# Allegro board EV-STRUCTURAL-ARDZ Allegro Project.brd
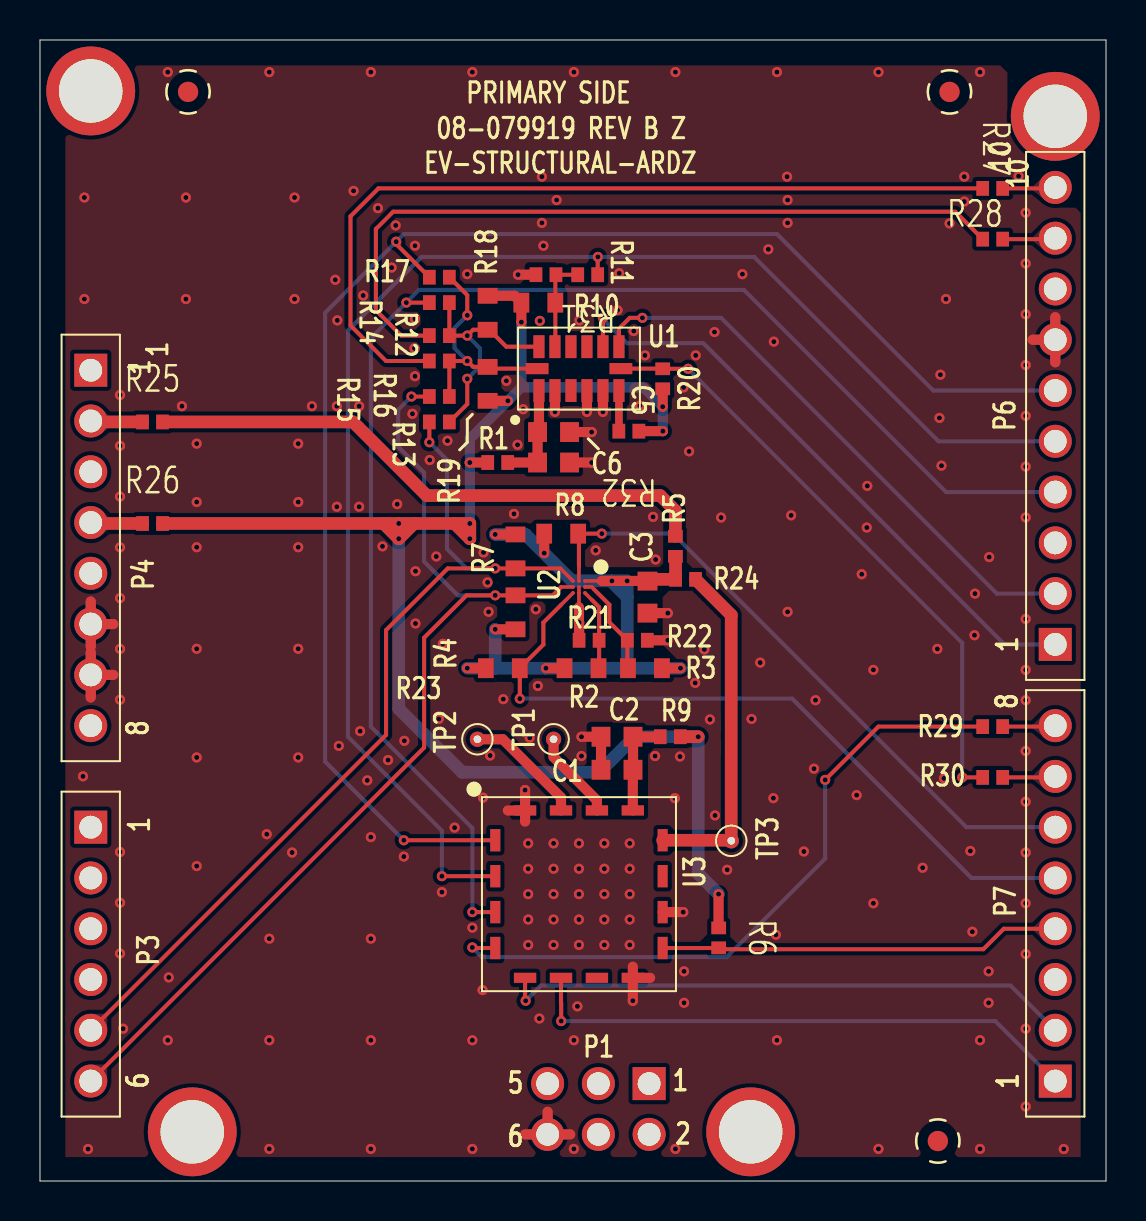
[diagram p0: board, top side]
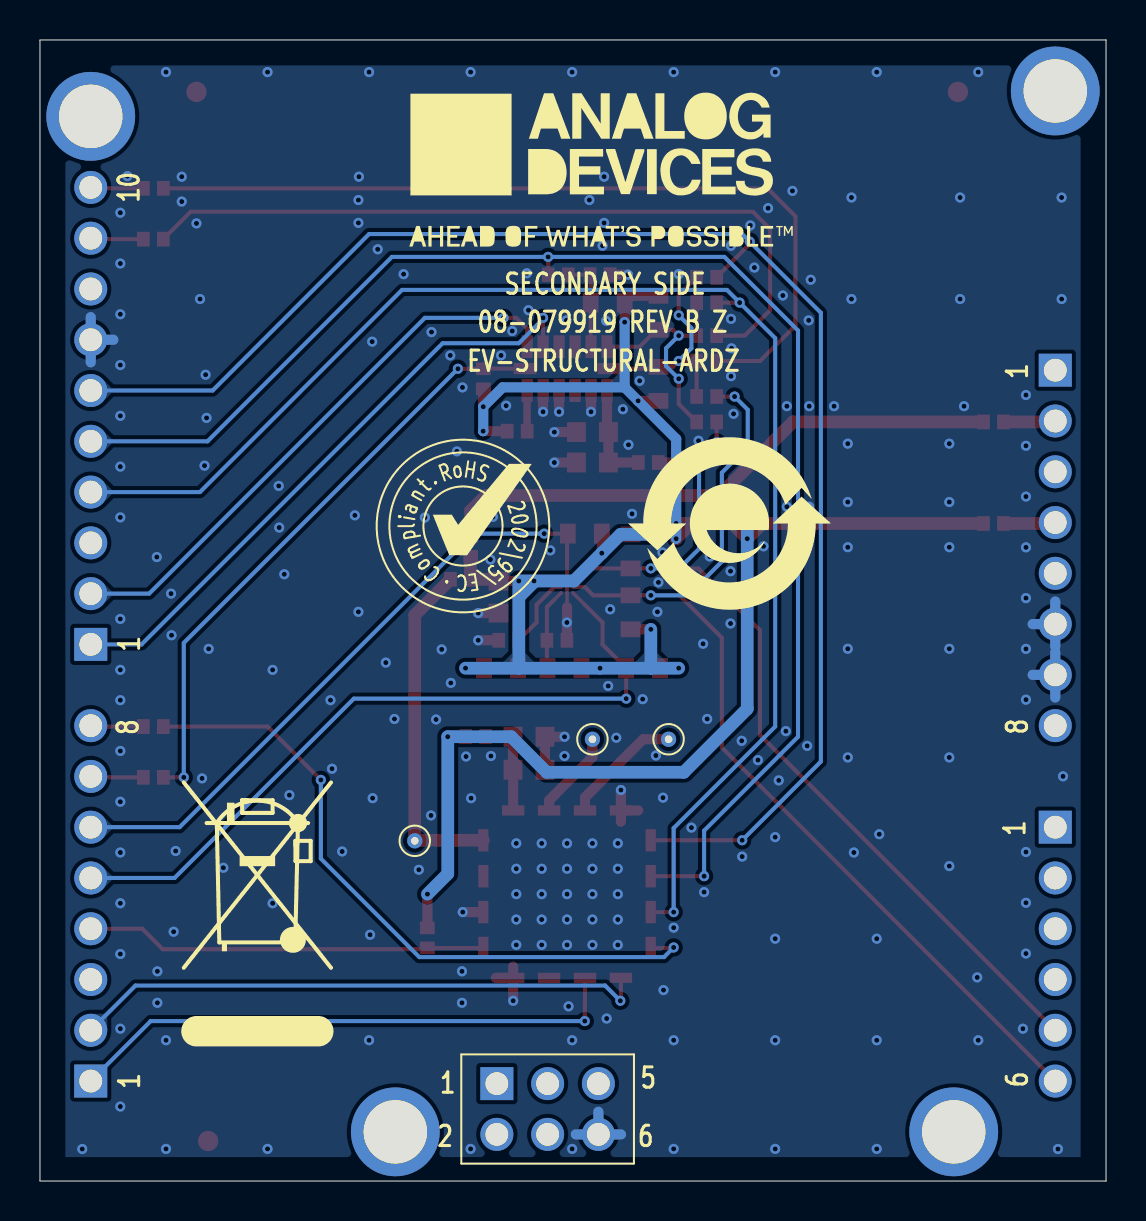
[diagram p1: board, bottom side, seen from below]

Outline 53.34 x 57.08 mm; copper layers: TOP, L2_GND, L3_GND, BOTTOM. Coordinates in mm from the lower left corner of the outline.
Outline path: 0,57.08 53.34,57.08 53.34,0 0,0 0,57.08

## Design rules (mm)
constraint set DEFAULT: min track width 0.203

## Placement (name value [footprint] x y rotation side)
C1  0.1uF  [C0603]  28.87 20.57 0 top
C2  10uF  [C0603]  28.87 22.23 0 top
C3  0.1uF  [C0603]  30.4 29.21 90 top
C5  0.1uF  [C0603]  25.7 37.46 180 top
C6  10uF  [C0603]  25.7 35.94 180 top
NOREF  -  [unnamed]  35.56 2.46 0 top
NOREF#2  -  [unnamed]  45.51 54.48 0 top
NOREF#3  -  [#2]  -30.49 -99.92 0 top
NOREF#4  -  [#2]  0 57.08 0 top
NOREF#5  -  [#2]  -30.49 -99.92 0 top
NOREF#6  -  [unnamed]  44.92 2 0 top
NOREF#7  -  [unnamed]  2.54 54.53 0 top
NOREF#8  -  [unnamed]  50.8 53.26 0 top
NOREF#9  -  [#2]  132.76 200.28 0 top
NOREF#10  -  [#2]  -35.57 -105 0 top
NOREF#11  -  [unnamed]  7.62 2.46 0 top
NOREF#12  -  [#2]  26.17 67.75 0 top
NOREF#13  -  [#2]  -14.58 80.5 0 top
NOREF#14  -  [#2]  -8.97 -45.09 0 top
NOREF#15  -  [#2]  53.34 -0.07 90 top
NOREF#16  -  [#2]  -35.57 -105 0 top
NOREF#17  -  [#2]  -35.57 -105 0 top
NOREF#18  -  [unnamed]  7.41 54.48 0 top
NOREF#19  -  [#2]  32.17 32.77 180 bottom
NOREF#20  -  [#2]  18.84 32.89 180 bottom
NOREF#21  -  [#2]  33.19 23.62 180 bottom
NOREF#22  -  [#2]  25.24 50.57 180 bottom
P1  SSQ-103-03-G-D  [CNSAMTECSSQ-103-XX-X-D]  30.48 4.87 180 bottom
P3  SSQ-106-03-G-S  [CNSAMTECSSQ-106-XX-X-S]  2.54 17.7 270 top
P4  SSQ-108-03-G-S  [CNSAMTECSSQ-108-XX-X-S]  2.54 40.56 270 top
P6  SSQ-110-03-G-S  [CNSAMTECSSQ-110-XX-X-S]  50.8 26.84 90 top
P7  SSQ-108-03-G-S  [CNSAMTECSSQ-108-XX-X-S]  50.8 5 90 top
R1  0  [R0402]  22.9 35.94 0 top
R2  4.7K  [R0603]  27.09 25.65 0 top
R3  4.7K  [R0603]  30.27 25.65 180 top
R4  4.7K  [R0603]  23.79 28.45 90 top
R5  0  [R0402]  31.79 31.75 270 top
R6  10K  [R0402]  33.96 12.16 270 top
R7  4.7K  [R0603]  23.79 31.5 270 top
R8  4.7K  [R0603]  26.08 32.38 0 top
R9  0  [R0402]  31.54 22.23 180 top
R10  4.7K  [R0603]  24.94 43.94 0 top
R11  0  [R0402]  25.32 45.34 0 top
R12  0  [R0402]  19.98 42.29 180 top
R13  0  [R0402]  19.98 37.97 180 top
R14  0  [R0402]  19.98 43.94 180 top
R15  0  [R0402]  19.98 41.02 180 top
R16  0  [R0402]  19.98 39.24 180 top
R17  0  [R0402]  19.98 45.21 180 top
R18  4.7K  [R0603]  22.4 43.43 270 top
R19  4.7K  [R0603]  22.4 39.88 90 top
R20  0  [R0402]  31.16 40.13 270 top
R21  0  [R0402]  27.48 27.05 0 top
R22  0  [R0402]  29.89 27.05 180 top
R23  4.7K  [R0603]  23.16 25.65 0 top
R24  0  [R0402]  32.3 30.1 180 top
R25  0  [R0402]  5.63 37.97 0 top
R26  0  [R0402]  5.63 32.89 0 top
R27  0  [R0402]  47.67 49.66 0 top
R28  0  [R0402]  47.67 47.12 0 top
R29  0  [R0402]  47.67 22.73 0 top
R30  0  [R0402]  47.67 20.19 0 top
R31  0  [R0402]  27.41 45.34 180 top
R32  0  [R0402]  29.46 37.51 180 top
TP1  TESTPAD  [TPC30D15]  25.7 22.1 270 top
TP2  TESTPAD  [TPC30D15]  21.89 22.1 270 top
TP3  TESTPAD  [TPC30D15]  34.59 17.02 270 top
U1  ADXL343BCCZ  [LGA14]  26.97 40.64 0 top
U2  MAX30210ENL+  [WLP9_0_97X0_97H0_50]  26.97 29.72 270 top
U3  ADIS16203CCCZ  [LGA16_D]  26.97 14.35 270 top

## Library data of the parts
C1 C3 C5 = CAP: User Part Number: UPN; Tolerance: 5; alternate symbols: (C0603); part number: CAP_SM-0.1UF,16V,5,E022221,C0603; tolerance: 5
C2 C6 = CAP: User Part Number: UPN; Tolerance: 10; alternate symbols: (C0603); part number: CAP_SM-10UF,10V,10,E020723,C0603; tolerance: 10
P1 = CN6P_ODD_EVEN: User Part Number: UPN; Tolerance: N/A; alternate symbols: (CNSAMTECSSQ-103-XX-X-D); part number: CN6P_ODD_EVEN_TH-SSQ-103-03-G-D,E020488,CNSAMTECSSQ-103-XX-X-D; tolerance: N/A
P3 = CN6P: User Part Number: UPN; Tolerance: N/A; alternate symbols: (CNSAMTECSSQ-106-XX-X-S); part number: CN6P_TH-SSQ-106-03-G-S,E020477,CNSAMTECSSQ-106-XX-X-S; tolerance: N/A
P4 P7 = CN8P_A: User Part Number: UPN; Tolerance: N/A; alternate symbols: (CNSAMTECSSQ-108-XX-X-S); part number: CN8P_A_TH-SSQ-108-03-G-S,E020478,CNSAMTECSSQ-108-XX-X-S; tolerance: N/A
P6 = CN10P: User Part Number: UPN; Tolerance: N/A; alternate symbols: (CNSAMTECSSQ-110-XX-X-S); part number: CN10P_TH-SSQ-110-03-G-S,E020479,CNSAMTECSSQ-110-XX-X-S; tolerance: N/A
R1 R5 R9 R11-R17 R20-R22 R24-R32 = RES: User Part Number: UPN; Tolerance: JUMPER; alternate symbols: (R0402); part number: RES_SM-0,E003438,1/10W,JUMPER,R0402; tolerance: JUMPER
R2-R4 R7 R8 R10 R18 R19 R23 = RES: User Part Number: UPN; Tolerance: 1; alternate symbols: (R0603); part number: RES_SM-4.7K,E010097,1/10W,1,R0603; tolerance: 1
R6 = RES: User Part Number: UPN; Tolerance: 1; alternate symbols: (R0402); part number: RES_SM-10K,E003751,1/10W,1,R0402; tolerance: 1
TP1-TP3 = NCTESTPAD: Tolerance: N/A; User Part Number: UPN; alternate symbols: (TPC30D15); part number: NCTESTPAD_TH-TESTPAD,E013464,TPC30D15; tolerance: N/A
U1 = ADXL343: Tolerance: N/A; User Part Number: UPN; alternate symbols: (LGA14); part number: ADXL343_SM-ADXL343BCCZ,E029512,LGA14; tolerance: N/A
U2 = ADMAX30210: User Part Number: UPN; Tolerance: N/A; alternate symbols: (WLP9_0_97X0_97H0_50); part number: ADMAX30210_SM-MAX30210ENL+,E062463,WLP9_0_97X0_97H0_50; tolerance: N/A
U3 = ADIS16203: User Part Number: UPN; Tolerance: N/A; alternate symbols: (LGA16_D); part number: ADIS16203_SM-ADIS16203CCCZ,E062334,LGA16_D; tolerance: N/A

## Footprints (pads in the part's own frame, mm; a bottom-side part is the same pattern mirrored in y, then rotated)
C0603
  rect 0.94x0.991 smd: 1(-0.8,0) 2(0.8,0)
CNSAMTECSSQ-103-XX-X-D
  rect 1.651x1.651 hole 1.143: 1(0,0)
  round 1.651 hole 1.143: 2(0,-2.54) 3(2.54,0) 4(2.54,-2.54) 5(5.08,0) 6(5.08,-2.54)
CNSAMTECSSQ-106-XX-X-S
  rect 1.651x1.651 hole 1.143: 1(0,0)
  round 1.651 hole 1.143: 2(2.54,0) 3(5.08,0) 4(7.62,0) 5(10.16,0) 6(12.7,0)
CNSAMTECSSQ-108-XX-X-S
  rect 1.651x1.651 hole 1.143: 1(0,0)
  round 1.651 hole 1.143: 2(2.54,0) 3(5.08,0) 4(7.62,0) 5(10.16,0) 6(12.7,0) 7(15.24,0) 8(17.78,0)
CNSAMTECSSQ-110-XX-X-S
  rect 1.651x1.651 hole 1.143: 1(0,0)
  round 1.651 hole 1.143: 2(2.54,0) 3(5.08,0) 4(7.62,0) 5(10.16,0) 6(12.7,0) 7(15.24,0) 8(17.78,0) 9(20.32,0) 10(22.86,0)
LGA14
  rect 0.559x1.143 smd: 1(-2,-1.097) 2(-1.2,-1.097) 3(-0.4,-1.097) 4(0.4,-1.097) 5(1.2,-1.097) 6(2,-1.097) 8(2,1.097) 9(1.2,1.097) 10(0.4,1.097) 11(-0.4,1.097) 12(-1.2,1.097) 13(-2,1.097)
  rect 1.143x0.559 smd: 7(2.097,0) 14(-2.097,0)
LGA16_D
  rect 1.118x0.508 smd: 1(-2.695,-4.186) 2(-0.898,-4.186) 3(0.898,-4.186) 4(2.695,-4.186) 9(2.695,4.186) 10(0.898,4.186) 11(-0.898,4.186) 12(-2.695,4.186)
  rect 0.508x1.118 smd: 5(4.186,-2.695) 6(4.186,-0.898) 7(4.186,0.898) 8(4.186,2.695) 13(-4.186,2.695) 14(-4.186,0.898) 15(-4.186,-0.898) 16(-4.186,-2.695)
R0402
  rect 0.635x0.737 smd: 1(-0.5,0) 2(0.5,0)
R0603
  rect 0.787x0.991 smd: 1(-0.85,0) 2(0.85,0)
TPC30D15
  round 0.762 hole 0.381: 1(0,0)
unnamed
  round 4.445 hole 3.175 unplated: (0,0)
WLP9_0_97X0_97H0_50
  round 0.178 smd: A1(-0.3,0.3) A2(0,0.3) A3(0.3,0.3) B1(-0.3,0) B2(0,0) B3(0.3,0) C1(-0.3,-0.3) C2(0,-0.3) C3(0.3,-0.3)

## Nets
GND: C1.1 C2.1 C3.1 C5.1 C6.1 P1.6(N6) P4.6 P4.7 P6.7 R11.1 R21.1 R22.1 U1.2 U1.4 U1.5 U2.B2 U2.B3 U3.8 U3.10 U3.16
VCC_TEMP: C3.2(N2) R2.1 R3.1 R4.1 R5.2(N2) R7.1 R8.1 R23.1 R24.2(N2) U2.A1(VDD)
VDD_1V8: R5.1 R25.2(N2)
VDD_3V3: R1.1 R6.1 R9.1 R10.1 R18.1 R19.1 R20.2(N2) R26.2(N2) R32.1
ADXL_SCL: R15.2(N2) R27.1
ADXL_SDA: R12.2(N2) R28.1
AUX_ADC: TP1.1(N1) U3.14
AUX_DAC: R24.1 TP3.1(N1) U3.12
INCL_DIO0: P7.2 U3.5
INCL_DIO1: P7.1 U3.6
INCL_RSTN: P7.4 R6.2(N2) U3.9
MEMS_INT1: P6.2 U1.8
MEMS_INT2: P6.1 U1.9
SPI_CS1: R29.1 U3.4
SPI_CS2: R20.1 R30.1 U1.7
SPI_MISO: P6.5 R31.1 U3.2
SPI_MOSI: P6.4 R14.2(N2) U3.3
SPI_MOSI_SDA: R12.1 R13.1 R14.1 R18.2(N2) U1.13
SPI_SCLK: P6.6 R17.2(N2) U3.1
SPI_SCLK_SCL: R15.1 R16.1 R17.1 R19.2(N2) U1.14
TEMP_CVT: P7.5 R23.2(N2) U2.C3
TEMP_INT: P7.6 R8.2(N2) U2.B1
TEMP_SCL: P3.6(N6) R4.2(N2) R16.2(N2) U2.C2
TEMP_SDA: P3.5 R7.2(N2) R13.2(N2) U2.C1
UNNAMED_7_ADIS16203_I52_VDD: C1.2(N2) C2.2(N2) R9.2(N2) U3.13
UNNAMED_7_ADMAX30210_I61_A0: R3.2(N2) R22.2(N2) U2.A2
UNNAMED_7_ADMAX30210_I61_A1: R2.2(N2) R21.2(N2) U2.A3
UNNAMED_7_ADXL343_I53_SDO: R10.2(N2) R11.2(N2) R31.2(N2) U1.12
UNNAMED_7_ADXL343_I53_VDDI: C5.2(N2) C6.2(N2) R1.2(N2) U1.1
UNNAMED_7_ADXL343_I53_VS: R32.2(N2) U1.6(VS)
UNNAMED_7_CN8PA_I118_N2: P4.2 R25.1
UNNAMED_7_CN8PA_I118_N4: P4.4 R26.1
UNNAMED_7_CN8PA_I140_N7: P7.7 R30.2(N2)
UNNAMED_7_CN8PA_I140_N8: P7.8(N8) R29.2(N2)
UNNAMED_7_CN10P_I139_N9: P6.9(N9) R28.2(N2)
UNNAMED_7_CN10P_I139_N10: P6.10 R27.2(N2)
VREF: TP2.1(N1) U3.15(VREF)

Pads without a net: P1 1 2 3 4 5; P3 1 2 3 4; P4 1 3 5 8; P6 3 8; P7 3; U1 3 10 11; U3 7 11

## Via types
v1: diameter 0.508, hole 0.254, TOP to BOTTOM, 280 vias

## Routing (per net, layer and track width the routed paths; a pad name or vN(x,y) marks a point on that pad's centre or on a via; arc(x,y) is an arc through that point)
GND: length 74
  TOP w0.178: 26.97,28.7 U2.B3 U2.B2
  TOP w0.508: P4.7 3.67,25.32 ; P4.7 2.54,24.19 ; P4.7 2.54,26.45 ; 25.4,2.33 25.4,3.46 ; 25.4,2.33 26.53,2.33 ; 25.4,2.33 24.27,2.33 ; U1.4 v1(27.37,38.48) ; C3.1 v1(31.41,28.41) ; 24.27,17.98 U3.16 ; U3.16 23.41,18.54 ; U3.16 v1(24.27,19.56) ; U3.8 30.53,10.16 ; U3.8 v1(29.66,9.02) ; U3.8 29.66,10.72 ; 2.54,26.73 P4.6 ; P4.6 3.67,27.86 ; P4.6 2.54,28.99 ; R22.1 v1(31.41,27.05) ; U1.2 v1(25.77,38.48) ; 50.8,40.95 P6.7 ; P6.7 50.8,43.21 ; P6.7 49.67,42.08 ; R11.1 v1(23.92,45.34) ; C6.1 v1(27.6,35.94) ; v1(27.09,22.23) C2.1 C1.1 ; R21.1 v1(26.98,27.94) 26.97,27.95 26.97,28.7 ; C5.1 v1(27.6,37.46) ; U3.10 v1(32.18,13.45) ; U1.5 v1(28.17,38.48)
  L2_GND w0.508: P4.7 3.67,25.32 ; P4.7 2.54,26.45 ; P4.7 2.54,24.19 ; 50.8,40.95 P6.7 ; P6.7 50.8,43.21 ; P6.7 49.67,42.08 ; 24.27,2.33 25.4,2.33 ; 25.4,2.33 25.4,3.46 ; 25.4,2.33 26.53,2.33 ; P4.6 2.54,28.99 ; P4.6 3.67,27.86 ; P4.6 2.54,26.73
  L3_GND w0.508: 2.54,26.73 P4.6 ; P4.6 2.54,28.99 ; P4.6 3.67,27.86 ; 25.4,2.33 25.4,3.46 ; 25.4,2.33 26.53,2.33 ; 25.4,2.33 24.27,2.33 ; P4.7 3.67,25.32 ; P4.7 2.54,24.19 ; P4.7 2.54,26.45 ; P6.7 50.8,43.21 ; P6.7 49.67,42.08 ; P6.7 50.8,40.95
  BOTTOM w0.508: P4.7 3.67,25.32 ; P4.7 2.54,26.45 ; P4.7 2.54,24.19 ; P4.6 3.67,27.86 ; P4.6 2.54,26.73 ; P4.6 2.54,28.99 ; 25.4,2.33 25.4,3.46 ; 25.4,2.33 26.53,2.33 ; 25.4,2.33 24.27,2.33 ; P6.7 50.8,43.21 ; P6.7 50.8,40.95 ; P6.7 49.67,42.08
  vias: v1(2.15,20.24) v1(2.22,49.2) v1(2.22,44.12) v1(2.41,1.6) v1(4.01,39.32) v1(4.01,36.78) v1(4.01,34.24) v1(4.01,31.7) v1(4.01,29.16) v1(4.01,26.62) v1(4.01,24.08) v1(4.01,16.46) v1(4.01,13.92) v1(4.01,11.38) v1(4.16,7.62) v1(6.39,55.47) v1(6.44,10.19) v1(6.39,7.04) v1(7.11,38.76) v1(7.3,49.2) v1(7.3,44.12) v1(7.84,36.89) v1(7.84,33.97) v1(7.84,31.71) v1(7.84,26.63) v1(7.84,21.19) v1(7.84,15.75) v1(11.35,17.35) v1(11.47,55.47) v1(11.47,12.12) v1(11.47,7.04) v1(11.47,1.61) v1(12.62,16.43) v1(12.74,49.2) v1(12.74,44.12) v1(12.92,36.89) v1(12.92,33.97) v1(12.92,31.71) v1(12.92,26.63) v1(12.92,21.19) v1(13.61,38.76) v1(14.78,45.09) v1(14.85,38.76) v1(14.85,33.73) v1(14.88,43.05) v1(14.95,21.77) v1(15.69,49.53) v1(15.97,38.76) v1(15.97,33.73) v1(16.02,22.5) v1(16.17,44.3) v1(16.38,20.04) v1(16.55,55.47) v1(16.55,17.2) v1(16.55,12.12) v1(16.55,7.04) v1(16.55,1.61) v1(16.91,48.67) v1(17.14,31.75) v1(17.42,21.06) v1(17.6,45.69) v1(17.8,47.8) v1(17.87,33.86) v1(18.23,22.02) v1(18.2,16.23) v1(18.64,38.38) v1(18.76,46.79) v1(18.76,43.13) v1(18.74,41.66) v1(18.76,40.26) v1(18.79,30.51) v1(18.79,27.89) v1(19.5,36.07) v1(19.83,31.24) v1(19.96,23.11) v1(20.16,26.87) v1(20.11,14.45) v1(20.39,37.03) v1(20.74,17.68) v1(21.38,45.36) v1(21.63,55.47) v1(21.63,12.67) v1(21.63,7.04) v1(21.63,1.61) v1(22.17,19.18) v1(22.14,9.55) v1(22.19,31.45) v1(22.4,29.95) v1(22.45,28.47) v1(22.52,21.29) v1(23.18,24.1) v1(23.34,40.03) v1(23.72,33.38) v1(23.89,36.83) v1(24.17,38.61) v1(24.43,16.89) v1(24.43,15.62) v1(24.43,14.35) v1(24.43,13.08) v1(24.43,11.81) v1(24.5,22.17) v1(24.81,28.6) v1(24.91,24.77) v1(25.01,43.03) v1(24.99,8.13) v1(25.11,50.24) v1(25.11,47.93) v1(25.19,46.79) v1(25.7,16.89) v1(25.7,15.62) v1(25.7,14.35) v1(25.7,13.08) v1(25.7,11.81) v1(25.85,49.07) v1(26.71,55.47) v1(26.71,7.04) v1(26.71,1.61) v1(26.97,16.89) v1(26.97,15.62) v1(26.97,14.35) v1(26.97,13.08) v1(26.97,11.81) v1(26.89,8.74) v1(26.99,43.05) v1(27.09,21.26) v1(27.81,31.55) v1(28.24,16.89) v1(28.24,15.62) v1(28.24,14.35) v1(28.24,13.08) v1(28.24,11.81) v1(28.9,43.56) v1(28.98,45.41) v1(29.51,16.89) v1(29.51,15.62) v1(29.51,14.35) v1(29.51,13.08) v1(29.51,11.81) v1(29.71,42.52) v1(30.02,38.79) v1(30.27,41.3) v1(30.68,33.22) v1(30.8,31.09) v1(30.78,21.26) v1(31.77,19.15) v1(31.79,55.47) v1(31.79,1.61) v1(32.02,21.23) v1(32.2,39.7) v1(32.23,10.49) v1(32.23,8.92) v1(32.48,36.5) v1(32.81,41.3) v1(32.78,24.92) v1(33.24,26.59) v1(33.52,23.09) v1(33.75,42.47) v1(33.78,18.29) v1(34.08,33.19) v1(34.38,15.57) v1(35.15,45.36) v1(35.6,23.11) v1(36.04,25.93) v1(36.44,46.61) v1(36.72,41.99) v1(36.7,19.15) v1(36.82,12.32) v1(36.87,55.47) v1(36.87,7.04) v1(37.38,50.24) v1(37.41,49.07) v1(37.41,47.93) v1(37.41,28.47) v1(37.59,33.3) v1(38.22,16.48) v1(38.73,20.62) v1(38.8,24.05) v1(40.86,19.3) v1(41.12,30.35) v1(41.37,32.69) v1(41.4,34.77) v1(41.7,25.57) v1(41.7,13.89) v1(41.95,55.47) v1(41.95,1.61) v1(44.16,15.67) v1(44.9,26.62) v1(45.05,40.34) v1(45.01,38.17) v1(45.11,35.79) v1(45.23,20.14) v1(45.33,44.12) v1(45.51,47.9) v1(46.25,50.24) v1(46.25,49) v1(46.55,16.51) v1(46.65,12.47) v1(46.76,27.3) v1(46.78,29.38) v1(47.03,55.47) v1(47.03,7.04) v1(47.03,1.61) v1(47.47,10.49) v1(47.47,8.92) v1(47.49,31.21) v1(48.96,50.27) v1(49.32,48.44) v1(49.32,45.9) v1(49.32,43.36) v1(49.32,40.82) v1(49.32,38.28) v1(49.32,35.74) v1(49.32,33.2) v1(49.32,28.12) v1(49.32,25.57) v1(49.32,24.05) v1(49.32,21.51) v1(49.32,18.97) v1(49.32,16.43) v1(49.32,13.89) v1(49.32,11.35) v1(49.32,7.62) v1(49.32,3.73) v1(51.22,1.6)
VCC_TEMP: length 37.2
  TOP w0.178: 28.11,30.02 U2.A1
  TOP w0.508: 28.11,30.02 v1(28.62,30.02) v1(29.38,30.02) 30.39,30.02 C3.2 ; R8.1 v1(25.23,31.41) ; R3.1 v1(32.05,25.65) ; R2.1 v1(25.32,25.65) ; R7.1 v1(22.78,32.35) ; R23.1 v1(21.38,25.65) ; R4.1 v1(22.78,27.6)
  TOP w0.635: C3.2 30.49,30.1 R24.2 31.8,31.24 R5.2
  BOTTOM w0.635: v1(22.78,32.35) 24.29,32.35 v1(25.23,31.41) 26.62,30.02 v1(28.62,30.02) ; 29.38,29.21 29.38,25.65 ; 29.38,29.21 v1(29.38,30.02) v1(28.62,30.02) ; 29.38,29.21 28.62,29.97 v1(28.62,30.02) ; 29.38,25.65 v1(32.05,25.65) ; 29.38,25.65 v1(25.32,25.65) 22.78,25.65 ; 22.78,25.65 v1(21.38,25.65) ; 22.78,25.65 v1(22.78,27.6)
VDD_1V8: length 28.8
  TOP w0.635: R5.1 31.79,33.53 31.03,34.29 19.35,34.29 15.66,37.97 R25.2
VDD_3V3: length 84.7
  TOP w0.508: v1(24.09,42.97) R10.1 23.74,44.28 R18.1 ; R1.1 v1(21.51,35.94) ; R19.1 v1(23.41,39.03) ; v1(33.95,14.35) 33.95,12.67 R6.1 ; R20.2 v1(31.16,38.73) ; R32.1 v1(31.17,37.51)
  TOP w0.635: v1(17.95,32.89) 18.71,32.89 ; v1(17.95,32.89) v1(17.95,32.13) ; v1(17.95,32.89) 17.19,32.89 ; 18.71,32.89 20.74,32.89 ; 18.71,32.89 v1(17.95,32.13) ; 20.74,32.89 v1(21.51,32.13) v1(21.51,32.89) 20.74,32.89 ; v1(17.95,32.13) 17.19,32.89 ; 17.19,32.89 R26.2 ; R9.1 v1(32.94,22.23)
  BOTTOM w0.508: 24.09,39.7 30.19,39.7 v1(31.16,38.73) 31.16,37.52 v1(31.17,37.51) ; 24.09,39.7 v1(24.09,42.97) ; 24.09,39.7 v1(23.41,39.03) 21.51,37.12 v1(21.51,35.94) v1(21.51,32.89) v1(21.51,32.13)
  BOTTOM w0.635: v1(33.95,14.35) 32.94,15.37 v1(32.94,22.23) 29.76,22.23 27.98,20.45 21.13,20.45 17.95,23.62 v1(17.95,32.13) v1(17.95,32.89)
ADXL_SCL: length 42.4
  TOP w0.203: R27.1 16.93,49.66 15.54,48.26 15.54,42.8 17.32,41.02 R15.2
ADXL_SDA: length 38.6
  TOP w0.203: R12.2 18.08,42.29 16.81,43.56 16.81,47.62 17.67,48.49 45.8,48.49 R28.1
AUX_ADC: length 4.5
  TOP w0.508: U3.14 27.87,19.04 25.7,21.21 TP1.1
AUX_DAC: length 17.3
  TOP w0.635: U3.12 34.56,17.05 TP3.1 34.59,28.31 R24.1
INCL_DIO0: length 28.9
  TOP w0.203: v1(24.3,9.02) 24.27,9.05 U3.5
  BOTTOM w0.203: P7.2 48.56,9.78 25.06,9.78 v1(24.3,9.02)
INCL_DIO1: length 28.1
  TOP w0.203: U3.6 26.07,8.9 26.08,8.89 v1(26.08,8)
  BOTTOM w0.203: P7.1 47.8,8 v1(26.08,8)
INCL_RSTN: length 20.1
  TOP w0.203: P7.4 48.22,12.62 47.2,11.6 34.03,11.6 R6.2 33.95,11.66 U3.9
MEMS_INT1: length 28.7
  TOP w0.203: v1(30.14,43.18) 29.51,43.18 28.97,42.64 U1.8
  BOTTOM w0.203: v1(30.14,43.18) 34.08,43.18 47.88,29.38 P6.2
MEMS_INT2: length 30.9
  TOP w0.203: v1(28.17,43.18) U1.9
  BOTTOM w0.203: P6.1 48.26,26.84 33.19,41.91 29.38,41.91 28.17,43.12 v1(28.17,43.18)
SPI_CS1: length 34
  TOP w0.203: v1(21.63,11.68) 21.66,11.66 U3.4 ; v1(39.29,20.07) 41.95,22.73 R29.1
  BOTTOM w0.203: v1(39.29,20.07) 39.29,16.13 34.36,11.2 22.12,11.2 v1(21.63,11.68)
SPI_CS2: length 30.5
  TOP w0.203: R30.1 v1(46.14,20.19) ; v1(32.43,40.63) R20.1 31.15,40.64 U1.7
  BOTTOM w0.203: v1(32.43,40.63) 46.14,26.92 v1(46.14,20.19)
SPI_MISO: length 73.5
  TOP w0.203: v1(27.91,46.23) 27.91,46.22 R31.1 ; U3.2 v1(20.11,15.25)
  BOTTOM w0.203: P6.5 44.95,37 35.73,46.23 v1(27.91,46.23) 19.09,46.23 15.41,42.54 15.41,22.22 20.11,17.53 v1(20.11,15.25)
SPI_MOSI: length 72.5
  TOP w0.203: R14.2 v1(18.33,43.94) ; U3.3 v1(21.63,13.45)
  BOTTOM w0.203: P6.4 45.34,34.46 35.22,44.58 18.97,44.58 v1(18.33,43.94) 16.55,42.16 16.55,22.73 21.63,17.65 v1(21.63,13.45)
SPI_MOSI_SDA: length 11.8
  TOP w0.203: v1(21.38,40.13) 21.38,38.87 R13.1 ; R14.1 R12.1 v1(21.38,42.29) 21.67,42.58 R18.2 22.48,42.58 23.33,41.74 U1.13
  BOTTOM w0.203: v1(21.38,42.29) 22.01,41.66 22.01,40.77 v1(21.38,40.13)
SPI_SCLK: length 76.5
  TOP w0.203: R17.2 17.82,46.87 v1(17.82,46.99) ; U3.1 v1(18.2,17.05)
  BOTTOM w0.203: P6.6 44.7,39.54 36.87,47.37 18.2,47.37 v1(17.82,46.99) 14.27,43.43 14.27,20.98 v1(18.2,17.05)
SPI_SCLK_SCL: length 11.4
  TOP w0.203: v1(21.38,43.31) 21.38,44.32 R17.1 ; U1.14 22.48,40.64 R19.2 21.67,40.73 v1(21.38,41.02) R15.1 R16.1
  BOTTOM w0.203: v1(21.38,41.02) 20.74,41.66 20.74,42.67 v1(21.38,43.31)
TEMP_CVT: length 36.9
  TOP w0.178: U2.C3 26.08,28.83
  TOP w0.203: v1(24.01,24.13) R23.2 25.19,26.84 25.19,27.94 26.08,28.83
  BOTTOM w0.203: P7.5 46.61,15.16 37.64,24.13 v1(24.01,24.13)
TEMP_INT: length 32.3
  TOP w0.178: U2.B1 26.97,30.73
  TOP w0.203: 26.97,30.73 26.97,32.35 R8.2 v1(28.11,32.38)
  BOTTOM w0.203: P7.6 46.35,17.7 31.67,32.38 v1(28.11,32.38)
TEMP_SCL: length 51.8
  TOP w0.178: U2.C2 26.08,29.72
  TOP w0.203: R16.2 v1(18.59,39.24) ; P3.6 19.22,21.68 19.22,27.18 21.34,29.3 v1(22.78,29.3) R4.2 25.66,29.3 26.08,29.72
  BOTTOM w0.203: v1(22.78,29.3) 20.91,29.3 19.22,30.99 19.22,35.43 17.93,36.73 17.93,38.58 v1(18.59,39.24)
TEMP_SDA: length 46.6
  TOP w0.178: U2.C1 26.04,30.65
  TOP w0.203: 26.04,30.65 R7.2 v1(22.78,30.65) 20.4,30.65 17.32,27.56 17.32,22.32 P3.5 ; R13.2 v1(19.48,36.96)
  BOTTOM w0.203: v1(22.78,30.65) 21.34,30.65 20.36,31.62 20.36,36.08 v1(19.48,36.96)
UNNAMED_7_ADIS16203_I52_VDD: length 5.1
  TOP w0.508: R9.2 C2.2 C1.2 29.66,20.56 U3.13
UNNAMED_7_ADMAX30210_I61_A0: length 5.2
  TOP w0.178: 27.73,29.59 27.6,29.72 U2.A2
  TOP w0.203: R3.2 29.39,25.69 R22.2 28.49,27.95 28.49,28.83 27.73,29.59
UNNAMED_7_ADMAX30210_I61_A1: length 4.1
  TOP w0.178: U2.A3 27.6,29.08
  TOP w0.203: 27.6,29.08 27.98,28.71 R21.2 27.98,25.69 R2.2
UNNAMED_7_ADXL343_I53_SDO: length 4.7
  TOP w0.203: U1.12 25.79,41.75 R10.2 25.79,45.31 R11.2 25.82,45.34 R31.2
UNNAMED_7_ADXL343_I53_VDDI: length 5.1
  TOP w0.508: U1.1 24.97,37.54 C5.2 C6.2 R1.2
UNNAMED_7_ADXL343_I53_VS: length 2
  TOP w0.381: U1.6 28.97,37.52 R32.2
UNNAMED_7_CN8PA_I118_N2: length 2.6
  TOP w0.635: P4.2 2.59,37.97 R25.1
UNNAMED_7_CN8PA_I118_N4: length 2.6
  TOP w0.635: R26.1 2.59,32.89 P4.4
UNNAMED_7_CN8PA_I140_N7: length 2.7
  TOP w0.203: R30.2 50.75,20.19 P7.7
UNNAMED_7_CN8PA_I140_N8: length 2.7
  TOP w0.203: R29.2 50.75,22.73 P7.8
UNNAMED_7_CN10P_I139_N9: length 2.7
  TOP w0.203: R28.2 50.75,47.12 P6.9
UNNAMED_7_CN10P_I139_N10: length 2.7
  TOP w0.203: P6.10 50.75,49.66 R27.2
VREF: length 6
  TOP w0.508: U3.15 26.07,19.19 23.16,22.1 TP2.1

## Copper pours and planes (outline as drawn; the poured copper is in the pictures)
GND on TOP: 1.47,8.51 1.75,8.51 1.9,8.35 1.59,7.94 1.51,7.54 1.56,7.23 1.7,6.95 1.74,6.88 1.64,6.78 1.44,6.78 1.27,6.95 1.27,8.31
GND on TOP: 51.28,13.82 51.99,13.82 52.07,13.73 52.07,11.61 51.89,11.43 51.45,11.43 51.28,11.61
GND on TOP: 33.01,23.11 33.01,21.29 34.31,21.29 34.31,23.11
GND on TOP: outline of 744 points within 1.27,1.2 52.07,55.81
GND on BOTTOM: 1.27,55.81 52.07,55.81 52.07,1.27 52.07,1.2 1.27,1.2
GND on L2_GND: 1.27,55.81 52.07,55.81 52.07,1.27 52.07,1.2 1.27,1.2
GND on L3_GND: 1.27,55.81 52.07,55.81 52.07,26.06 52.07,1.2 1.27,1.2

Small or netless copper shapes (teardrops, artwork), in the pictures only: 37 on TOP, 37 on BOTTOM

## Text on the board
Ref Des/Silkscreen Bottom: SECONDARY SIDE | EV-STRUCTURAL-ARDZ | 08-079919 REV B Z
User.Comments: COMPONENT KEEPOUT AREA | COMPONENTS GREATER THAN 1.5MM | 6.    THE FOLLOWING PARTS ARE DNI(DO NOT INSTALL): | DIRECTIVE 2002/95/EC). | B. P4 | C. P6 | D. P7 | WITH LEAD-FREE AND RoHS PCB ASSEMBLY STANDARDS (EU RoHS | 5.    DO NOT TRIM EXCESS PINS FOR THE FOLLOWING LOCATIONS | A. P3 | -P1 | -R2,R3,R10,R23 | -R13,R14,R16,R17,R24,R30,R31 | 4.    RoHS COMPLIANCE. ASSEMBLY VENDOR SHOULD ASSURE COMPLIANCE
Ref Des/Silkscreen Top: PRIMARY SIDE | EV-STRUCTURAL-ARDZ | 08-079919 REV B Z | 1
PAGE_OUTLINE: B | ECR-116882 | 05DEC23 | E. REYTA | EV-STRUCTURAL-ARDZ
DIMENSION: -0.10IN | 2.15IN | "0" | (REF) | -0.30IN | 1.80IN
User.10: L2 Internal GND | 08-      -07
User.11: L3 Internal GND | 08-      -08
User.12: FAB NOTES REVISION: 2ND NOVEMBER 2022 | 8.   IMPEDANCE REQUIREMENTS: IF NO STACKUP IS DEFINED, THE VENDOR IS ALLOWED TO ADJUST THE DIELECTRIC | 13.  PLATING SPECIFICATION: | 9.   FILLET OPTIONS TO ENHANCE RELIABILITY AT PAD JUNCTIONS WHERE SPACING PERMITS. | 10.  THIEVING: | 11.  LAYER TO LAYER REGISTRATION SHALL BE WITHIN 0.003 INCHES. | 12.  DRILL SIZES ARE FINISHED HOLE SIZES. ALL HOLES SHALL BE LOCATED WITHIN 0.005 INCHES DTP,UNLESS SPECIFIED. | 14.  SURFACE FINISH: | 15.  SOLDERMASK: | 1.   DIMENSIONS ARE IN INCHES (EXCEPT WHERE NOTED). | ALL DOCUMENTS & SPECIFICATIONS REFERRED TO BELOW SHOULD BE THE LATEST REVISIONS. | 2.  BOARD MATERIAL:(USE CHECKED ITEMS) | 3.   ALL LAMINATES & BONDING MATERIALS SHOULD BE SELECTED FROM IPC-4101 OR IPC-4103,(TG>170 DEGC TD>300 DEGC) | 4.   REFER TO IPC-6010 SERIES, CLASS 2 FOR FABRICATION. | 5.   REFER TO LAMINATION DIAGRAM FOR OVERALL BOARD THICKNESS, TOLERANCE APPLIES AFTER ALL LAMINATION AND PLATING | 6.   BOW & TWIST NOT TO EXCEED 0.0075 INCHES (0.75%) PER LINEAR INCH AND SHOULD BE MEASURED PER IPC-TM-650, METHOD 2.4.22. | 7.   ACCEPTABILITY PER ADI SPECIFICATION TST00115. | 16.  APPLY SILKSCREEN TO BOTH SIDES USING A NON-CONDUCTIVE, EPOXY BASED INK PER ARTWORK. | ( ) FILLETS ALLOWED | (X) FILLETS NOT ALLOWED | ( ) VENDOR MAY ADD THIEVING TO COMPENSATE FOR LOW COPPER DENSITY AREAS MAINTAINING A MINIMUM | ( ) VENDOR MAY NOT ADD THIEVING TO COMPENSATE FOR LOW COPPER DENSITY AREAS. | (X) LPI | ( ) OTHER_________ | COLOR | ( ) GREEN | (X) OTHER_________ | (X) WHITE | ( ) OTHER | HINDER PROPER SOLDER WICKING. BARREL RELIEF ON SOLDERMASK ALLOWED IN UNFILLED VIA IN PAD HOLES. | (X) REFER TO LAMINATION DIAGRAM FOR FINISHED COPPER WEIGHT/THICKNESS REQUIRMENTS | (X) IMMERSION GOLD (ENIG) 1.58-3.94 MICRO INCHES OVER 118-236 MICRO INCHES MIN. OF ELECTROLESS NICKEL PER IPC-4552 | ( ) OSP (ORGANIC SOLDERABILITY PRESERVATIVE) | ( ) IMMERSION SILVER | ( ) SOFT WIRE BONDABLE GOLD 30-50 MICRO INCHES OF SOFT WIRE | ( ) EDGE CONNECTOR FINGERS ARE TO BE PLATED WITH 100 MICRO-INCHES(.0001") OF LOW STRESS | ( ) OTHER: | THICKNESS & TRACE WIDTHS TO MEET THE IMPEDANCE REQUIREMENT. IF SPECIFIED, THE VENDOR MUST | TRACE WIDTH & SPACING THAT IMPACT THE REQUIREMENTS MUST HAVE WRITTEN APPROVAL FROM ADI. | MINIMUM BARREL PLATING OF 0.001 INCHES. PLATED HOLES SHALL NOT BE ROUGH OR IRREGULAR SO AS TO | SOLDERMASK OVER BARE COPPER OR BARE GOLD (BOTH SIDES) TO MEET IPC-SM-840. | IF PRESENT,DO NOT MODIFY SOLDERMASK DEFINED PADS (MASK OPENINGS LESS THAN COPPER PAD) WITHOUT APPROVAL. | MEET THE REQUIREMENTS LISTED IN THE IMPEDANCE TABLE. ANY ADJUSTMENT MADE TO THE DEFINED STACKUP, | PROCESSES. FINISHED THICKNESS MEASURED FROM TOP COPPER TO BOTTOM COPPER. | (X)  ISOLA 370HR OR EQUIVALENT | ( )  ISOLA-FR408HR OR EQUIVALENT | ( )  ISOLA IS410 | ( )  MEGTRON 6 | ( )  NELCO-4000-13 | ( )  ROGERS 4350B | ( ) ROGERS 3003 | ( ) ARLON 85N | ( ) EM370D | ( )  OTHER ________________________ | X | UL FLAMMABILITY RATING 94V-0. BOARD MATERIAL & CONSTRUCTION SHALL MEET THE REQUIREMENTS OF UL796/UL796F. | BONDABLE GOLD OVER 100-150 MICRO INCHES OF NICKEL | NICKEL UNDER 30 MICRO-INCHES (.0003') OF GOLD | 0.100 INCH CLEARANCE FROM ALL COPPER FEATURES, | THE STARTING COPPER WEIGHT/THICKNESS CAN VARY AS LONG AS THE FINISHED COPPER | WEIGHT/THICKNESS IS NOT LESS THAN THE SPECIFIED VALUE. | UNLESS OTHERWISE SPECIFIED | BLUE | HOMOGENOUS MATERIALS IN THIS BOARD SHALL BE COMPLAINT WITH THE EU DIRECTIVE 2002/95/EC | WORKMANSHIP SHALL CONFORM TO IPC-A-600, CLASS 2. | 21.  INTENTIONAL SHORTS: | 17.  FINAL ELECTRICAL TEST TO BE PERFORMED USING PROVIDED IPC-D-356A NETLIST OR ODB++ FORMAT FILE. | 22.  PEMNUTS: | 23.  MANUFACTURER TO ETCH/STAMP WITH PERMANENT NON-CONDUCTIVE INK | ON SECONDARY SIDE UNLESS OTHERWISE SPECIFIED: | 18.  A TIME DOMAIN REFLECTOMETER REPORT (TDR) FOR EACH IMPEDANCE CONTROLLED LAYER & A CERTIFICATE | 19.  IF PRESENT, ALL BLIND/BURIED VIAS WITH AN ASPECT RATIO <1:1 TO BE PLATED SHUT WITH COPPER WHEN | 20.  FOR VIA FILL INFORMATION REFER TO DRILL CHART: | 24.  MINIMUM DESIGN LINE WIDTH IS .007 INCH. | 25.  MINIMUM DESIGN LINE SPACING IS .004 INCH. | 26.  BOARDS TO BE SHIPPED SINGULATED AFTER FABRICATION PROCESS | SMOOTHEN EDGES AND FREE FROM BURRS AFTER DEPANELIZATION PROCESS | IS ACCEPTABLE, ALL OTHER INSTANCES MUST BE REPORTED. | IF AN INTENTIONAL SHORT REPORT IS SUPPLIED AND DOES NOT MATCH THE FAB DATA THEN | THE PCB SHALL HAVE A VERIFICATION STAMP. | ( )  NON-CONDUCTIVE EPOXY FILL ALL 0.XXXX INCHES DRILLED VIAS | ( )  COPPER FILL ALL 0.XXXX INCHES DRILLED VIAS | ( ) PEMNUTS TO BE INSTALLED BY FABRICATOR | ( ) PEMNUTS NOT TO BE INSTALLED BY FABRICATOR | ( ) NOT APPLICABLE | USED AS VIA-IN-PAD OR AS A STACKED VIA. BLIND/BURIED VIAS WITH AN ASPECT RATIO >1:1 TO BE FILLED | A. UL CODE-FLAMMABILITY RATING FOR THOSE APPROVED MATERIALS(IF APPLICABLE) | B. DATE CODE | C. LOT NUMBER | D. MANUFACTURER LOGO | CAN'T BE PERFORMED BECAUSE THE TRACE LENGTH IS TOO SHORT ON THE OUTER LAYERS AT THE PIN ESCAPES | ADI APPROVAL IS REQUIRED. | OF COMPLIANCE SHALL BE PROVIDED BY VENDOR AT TIME OF SHIPMENT. INSTANCES WHERE TDR TESTING | WITH NON-CONDUCTIVE EPOXY. | TOOLING: | FINISH: | NOTES: | MATERIAL: | TESTING: | MISCELLANEOUS: | DIA MAX | TENTED VIA
User.19: L2 GND | 08-      -07
User.20: L3 GND | 08-      -08
User.35: PER ECR-094468 | B | 28MAY20 | PD
User.37: PAGE 1 OF 5 | TOP SIDE VIEW | VIEW OF SILKSCREEN, PINS, VIAS, | ETCH AND REFERENCE INFORMATION. | TEMPLATE NOTES. | 01.COMPONENTS ARE PLACED ON THIS SIDE. | 02.CONNECTORS P1,P2.P4 & P5 ARE PLACED | ON THIS SIDE OF THE BOARD. | 03.IF THE BOARD NEEDS TO BE INCREASED | IT CAN BE INCREASED IN THE DIRECTION | OF THE ARROWS. | 04.THE BOARD IS SET-UP AS A 4 LAYER | BOARD. MAKE SURE ANY SUBSEQUENT CHANGES, | MANUAL OR AUTOMATIC, DO NOT RESULT IN | ANY UNINTENDED CONSEQUENCES. | 05.THE EXISTING ROUTING CAN BE ALTERED AS | IS ROUTED TO CLOSE THE NETS ON THE | TEMPLATE BOARD.
User.38: PAGE 2 OF 5 | BOTTTOM SIDE VIEW | VIEW OF SILKSCREEN, PINS, VIAS, | ETCH AND REFERENCE INFORMATION. | TEMPLATE NOTES. | 01.COMPONENTS ARE PLACED ON THIS SIDE. | 02.CONNECTORS P3 IS PLACED ON THIS SIDE. THE | OTHER CONNECTORS ARE SOLDERED THIS SIDE. | 03.THE TEMPLATE IS VIEWED LOOKING FROM THE | TOP SIDE OF THE BOARD. THE RESULT IS | THAT TEXT IS MIRRORED. | 04.THE BOARD IS SET-UP AS A 4 LAYER | BOARD. MAKE SURE ANY SUBSEQUENT CHANGES, | MANUAL OR AUTOMATIC, DO NOT RESULT IN | ANY UNINTENDED CONSEQUENCES.
User.39: PAGE 3 OF 5 | PCB FAB SHEET 1 | NCDRILL LEGEND, APPROPRIATE | DETAILS AND OUTLINE DIMENSION NOTES. | 01. EACH TIME THE NC DRILL LEGEND | IS RUN, THE HOLE CHART MUST BE | CHECKED TO ASSURE THE TOLERANCES | & NOTES CORRESPOND TO THE RIGHT | PADSTACKS.
User.40: PAGE 4 OF 5 | PCB FAB SHEET 2 | FABRICATION NOTES. ALTER DEPENDING ON THE | REQUIREMENTS OF THE DESIGN.
User.41: TEMPLATE REVISION HISTORY | TEMPLATE BOARDS FOR EVAL PROVIDE INFORMATION IN THE | 5-VIEW "PDF FORMAT" FOR EVAL ENGINEERING | REFERENCE; ALONG WITH EMBEDDED ALLEGRO | PROPERTIES FOR PCB DESIGN USE. | THEY MAINTAIN A SEPARATE TITLE BLOCK AND PART | NUMBER FOR REVISION TRACKING, INDEPENDENT OF | THE ACTUAL MANUFACTURED DUT-SPECIFIC BOARD | DESIGN. | TEMPLATE BOARDS DISPLAY AS "FILE VIEWS", AND | DUT-SPECIFIC APPLICATION BOARDS ARE | MANUFACTURED FROM ARTWORK "FILM VIEWS"AND NC | DATA. | AND TITLE BLOCK CONTENT IS TRACKING THE | MANUFACTURED BOARD PART NUMBER AND REV, | AND NOT THE TEMPLATE BOARD PART NUMBER AND | REV. | PAGE 5 OF 5 | MAKE SURE THE DUT-SPECIFIC BOARD INFORMATION | REV.A (20APR20) | 1. INITIAL RELEASE. | REV.B (28MAY20) PER ECR-094468 | 1. BRING FILES INTO TEMPLATE FORMAT.
User.45: 1 | FABRICATION | 09-012345-01 | A | FIGURE | SIZE | 10.0 | 15.0 | 45.0 | 125.0 | PLATED | NON-PLATED | FINISHED HOLES IN MILS | ALL UNITS ARE IN MILS | QTY | 280 | 3 | 38 | 4 | TOLERANCE/NOTES
